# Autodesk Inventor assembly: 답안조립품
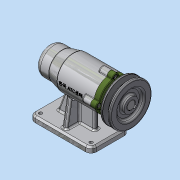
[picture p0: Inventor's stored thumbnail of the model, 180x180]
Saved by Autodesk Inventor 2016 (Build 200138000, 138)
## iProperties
Created: 2019-07
Part Number: 답안조립품
Document SubType Name: Assembly
Designer: MIRAE
Author: MIRAE
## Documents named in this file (12)
- C:\Users\MIRAE\Desktop\490704V1021\답안조립품.iam
- C:\Users\MIRAE\Desktop\490704V1021\본체.ipt
- C:\Users\MIRAE\Desktop\490704V1021\공용부품\V벨트풀리.ipt
- C:\Users\MIRAE\Desktop\490704V1021\공용부품\멈춤나사 M3.ipt
- C:\Users\MIRAE\Desktop\490704V1021\공용부품\베어링 6004.ipt
- C:\Users\MIRAE\Desktop\490704V1021\공용부품\베어링 51202.ipt
- C:\Users\MIRAE\Desktop\490704V1021\공용부품\볼트 M4.ipt
- C:\Users\MIRAE\Desktop\490704V1021\공용부품\어댑터슬리브.ipt
- C:\Users\MIRAE\Desktop\490704V1021\공용부품\오일 실.ipt
- C:\Users\MIRAE\Desktop\490704V1021\공용부품\축.ipt
- C:\Users\MIRAE\Desktop\490704V1021\공용부품\커버.ipt
- C:\Users\MIRAE\Desktop\490704V1021\공용부품\키 5 x 5 x 16.ipt
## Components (1 placed, 1 different names)
1. V벨트풀리:1
